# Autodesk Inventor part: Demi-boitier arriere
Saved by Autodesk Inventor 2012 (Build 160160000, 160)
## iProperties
Created: 2013-08
Part Number: Demi-boitier arriere
Material: Default
Document SubType Name: Modeling
Designer: hilarion
Density: 1 g/cm^3
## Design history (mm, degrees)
node "Demi-boitier arriere1"
node "Demi-boitier arriere"
node "Base1"
